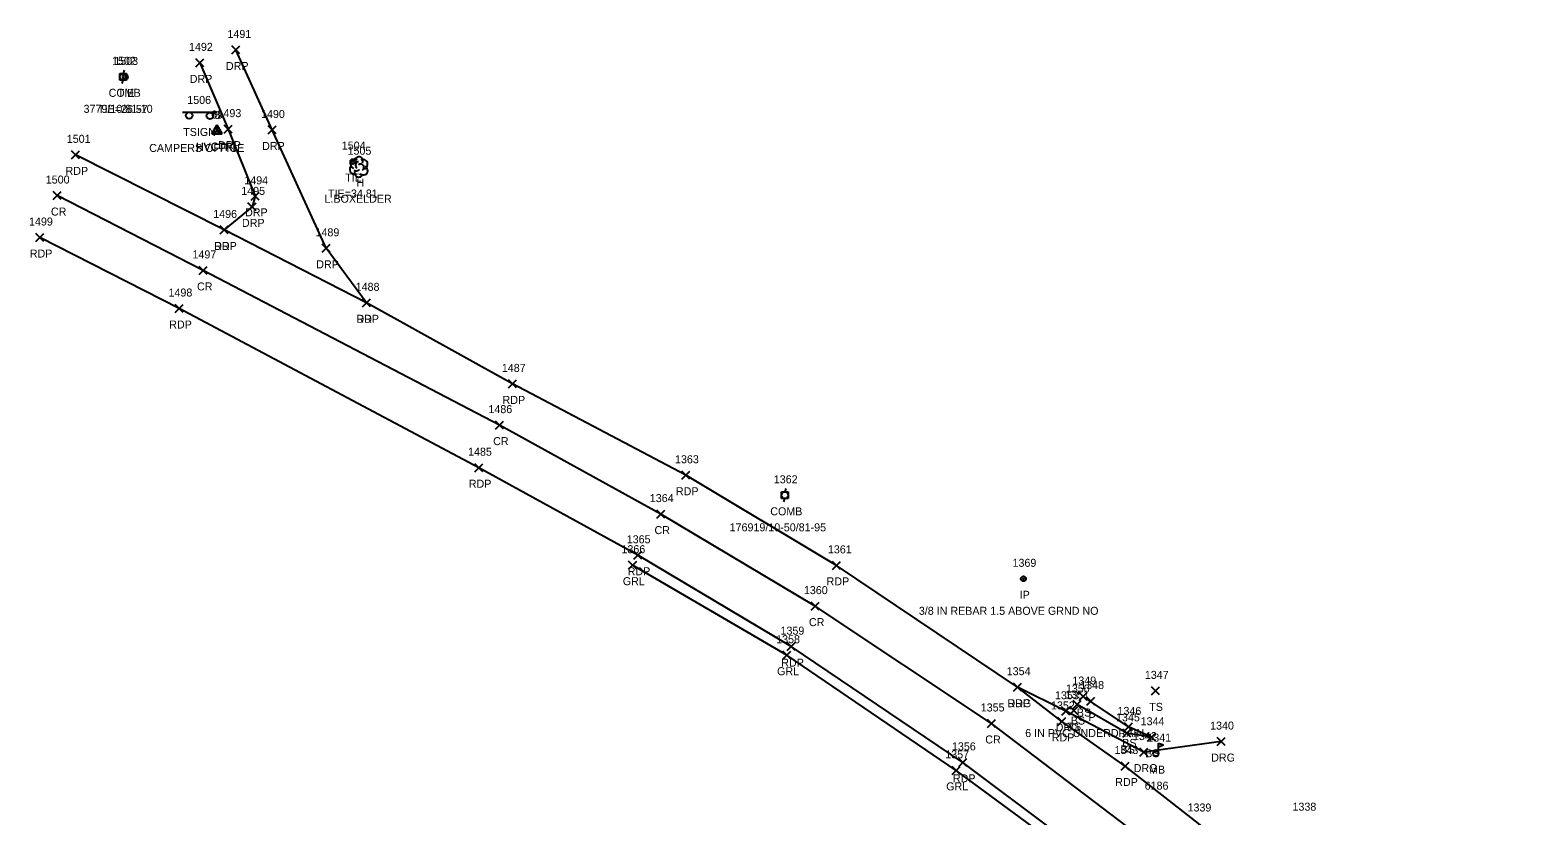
# Model space of a CAD drawing. Extents: x 1401404 to 1403982, y 557481 to 559873.
# Drawn here: x 1402764 to 1403136.9, y 558828.6 to 559024.9 of the extents above; entities that cross this region are included whole.
import ezdxf

# ---------------------------------------------------------------- set-up
doc = ezdxf.new("R2010")
doc.units = 0
for name, color, linetype in [('C_A', 7, 'Continuous'), ('C_C', 7, 'Continuous'), ('C_I', 7, 'Continuous'), ('CBP', 7, 'Continuous'), ('CPSM', 7, 'Continuous'), ('D_A', 7, 'Continuous'), ('D_C', 7, 'Continuous'), ('D_I', 7, 'Continuous'), ('D_TIC', 7, 'Continuous'), ('L_A', 7, 'Continuous'), ('L_C', 7, 'Continuous'), ('L_I', 7, 'Continuous'), ('L_TIC', 7, 'Continuous'), ('LELB', 7, 'Continuous'), ('LMB', 7, 'Continuous'), ('LTD', 7, 'Continuous'), ('M_A', 7, 'Continuous'), ('M_C', 7, 'Continuous'), ('M_I', 7, 'Continuous'), ('MPIR', 7, 'Continuous'), ('P_A', 7, 'Continuous'), ('P_I', 7, 'Continuous'), ('P_TIC', 7, 'Continuous'), ('PET', 7, 'Continuous'), ('PRC', 7, 'Continuous'), ('R_A', 7, 'Continuous'), ('R_I', 7, 'Continuous'), ('R_TIC', 7, 'Continuous'), ('RDG', 7, 'Continuous'), ('RDP', 7, 'Continuous'), ('RGR', 7, 'Continuous'), ('S_A', 7, 'Continuous'), ('S_C', 7, 'Continuous'), ('S_I', 7, 'Continuous'), ('SSGN', 7, 'Continuous'), ('U_A', 7, 'Continuous'), ('U_C', 7, 'Continuous'), ('U_I', 7, 'Continuous'), ('UP', 7, 'Continuous')]:
    doc.layers.add(name, color=color, linetype=linetype)

msp = doc.modelspace()

# ---------------------------------------------------------------- linework, layer by layer
at = {"layer": 'CBP'}
for centre, radius in [((1402787.85, 559013.09), 0.625), ((1402787.85, 559013.09), 0.0833), ((1402844.7, 558991.95), 0.625), ((1402844.7, 558991.95), 0.0833)]:
    msp.add_circle(centre, radius, dxfattribs=at)
at = {"layer": 'CPSM'}
for p, q in [((1402809.49, 558998.86), (1402810.74, 559001.02)), ((1402809.49, 558998.86), (1402810.74, 558999.58)), ((1402809.57, 558998.97), (1402810.82, 559001.13)), ((1402809.57, 558998.97), (1402810.82, 558999.69)), ((1402811.99, 558998.86), (1402810.74, 559001.02)), ((1402810.74, 558999.58), (1402810.74, 559001.02)), ((1402810.74, 558999.58), (1402810.74, 558999.58)), ((1402810.74, 558999.58), (1402811.99, 558998.86)), ((1402812.07, 558998.97), (1402810.82, 559001.13)), ((1402810.82, 558999.69), (1402810.82, 559001.13)), ((1402810.82, 558999.69), (1402810.82, 558999.69)), ((1402810.82, 558999.69), (1402812.07, 558998.97)), ((1402809.49, 558998.86), (1402811.99, 558998.86)), ((1402809.57, 558998.97), (1402812.07, 558998.97))]:
    msp.add_line(p, q, dxfattribs=at)
at = {"layer": 'D_TIC'}
for points in [[(1403028.12, 558856.1), (1403030.12, 558858.1)], [(1403030.12, 558856.1), (1403028.12, 558858.1)]]:
    msp.add_lwpolyline(points, dxfattribs=at)
at = {"layer": 'L_TIC'}
for points in [[(1403026.17, 558857.22), (1403028.17, 558859.22)], [(1403028.17, 558857.22), (1403026.17, 558859.22)], [(1403044.28, 558858.64), (1403046.28, 558860.64)], [(1403046.28, 558858.64), (1403044.28, 558860.64)], [(1403023.83, 558853.72), (1403025.83, 558855.72)], [(1403025.83, 558853.72), (1403023.83, 558855.72)], [(1403024.63, 558855.23), (1403026.63, 558857.23)], [(1403026.63, 558855.23), (1403024.63, 558857.23)], [(1403037.5, 558849.63), (1403039.5, 558851.63)], [(1403039.5, 558849.63), (1403037.5, 558851.63)], [(1403037.07, 558848.03), (1403039.07, 558850.03)], [(1403039.07, 558848.03), (1403037.07, 558850.03)], [(1403043.23, 558847.05), (1403045.23, 558849.05)], [(1403045.23, 558847.05), (1403043.23, 558849.05)], [(1403043.23, 558847.05), (1403045.23, 558849.05)], [(1403045.23, 558847.05), (1403043.23, 558849.05)]]:
    msp.add_lwpolyline(points, dxfattribs=at)
at = {"layer": 'LELB'}
for points in [[(1403044.23, 558848.05), (1403038.5, 558850.63), (1403027.17, 558858.22)], [(1403044.23, 558848.05), (1403038.07, 558849.03), (1403025.63, 558856.23)]]:
    msp.add_lwpolyline(points, dxfattribs=at)
at = {"layer": 'LMB'}
for p, q in [((1403045.33, 558843.95), (1403045.33, 558843.95)), ((1403045.98, 558846.55), (1403047.27, 558846.16)), ((1403045.98, 558843.95), (1403045.98, 558846.55)), ((1403045.98, 558845.65), (1403047.26, 558846.15))]:
    msp.add_line(p, q, dxfattribs=at)
msp.add_circle((1403045.33, 558843.95), 0.656, dxfattribs=at)
at = {"layer": 'LTD'}
msp.add_line((1402846.14, 558990.65), (1402846.14, 558990.65), dxfattribs=at)
msp.add_line((1402846.14, 558990.65), (1402846.14, 558990.65), dxfattribs=at)
msp.add_arc((1402846.19, 558992.09), 1.05, 335.5272, 180.9563, dxfattribs=at)
for centre, major_axis, ratio, start_param, end_param in [((1402845.35, 558991.32), (1.21, -0.51), 0.895232, 1.570796, 4.712389), ((1402847.18, 558991.24), (-1.14, -0.48), 0.949671, 1.570796, 4.712389), ((1402845.06, 558989.94), (0.58, -1.04), 0.959034, 3.141593, 6.283185), ((1402846.14, 558989.15), (0.26, 1.06), 0.942809, 1.570796, 4.712389), ((1402845.68, 558989.9), (-0.625, -0.083), 0.423636, 0, 3.141593), ((1402845.93, 558991.11), (-0.208, -0.792), 0.645439, 3.141593, 6.283185), ((1402846.64, 558990.48), (-0.5, 0.667), 0.989748, 3.141593, 6.283185), ((1402847.14, 558989.82), (-1.09, 0.79), 0.841452, 1.570796, 4.712389)]:
    msp.add_ellipse(centre, major_axis=major_axis, ratio=ratio, start_param=start_param, end_param=end_param, dxfattribs=at)
at = {"layer": 'MPIR'}
for radius in [0.625, 0.0833]:
    msp.add_circle((1403012.26, 558887.65), radius, dxfattribs=at)
at = {"layer": 'P_TIC'}
for points in [[(1402774.42, 558992.62), (1402776.42, 558994.62)], [(1402776.42, 558992.62), (1402774.42, 558994.62)], [(1402769.83, 558982.44), (1402771.83, 558984.44)], [(1402771.83, 558982.44), (1402769.83, 558984.44)], [(1402765.49, 558971.95), (1402767.49, 558973.95)], [(1402767.49, 558971.95), (1402765.49, 558973.95)], [(1402811.56, 558973.84), (1402813.56, 558975.84)], [(1402813.56, 558973.84), (1402811.56, 558975.84)], [(1402806.32, 558963.73), (1402808.32, 558965.73)], [(1402808.32, 558963.73), (1402806.32, 558965.73)], [(1402800.33, 558954.21), (1402802.33, 558956.21)], [(1402802.33, 558954.21), (1402800.33, 558956.21)], [(1402847.1, 558955.63), (1402849.1, 558957.63)], [(1402849.1, 558955.63), (1402847.1, 558957.63)], [(1402883.61, 558935.36), (1402885.61, 558937.36)], [(1402885.61, 558935.36), (1402883.61, 558937.36)], [(1402880.32, 558925.06), (1402882.32, 558927.06)], [(1402882.32, 558925.06), (1402880.32, 558927.06)], [(1402875.18, 558914.42), (1402877.18, 558916.42)], [(1402877.18, 558914.42), (1402875.18, 558916.42)], [(1402926.93, 558912.53), (1402928.93, 558914.53)], [(1402928.93, 558912.53), (1402926.93, 558914.53)], [(1402920.63, 558902.82), (1402922.63, 558904.82)], [(1402922.63, 558902.82), (1402920.63, 558904.82)], [(1402914.87, 558892.53), (1402916.87, 558894.53)], [(1402916.87, 558892.53), (1402914.87, 558894.53)], [(1402964.57, 558890.01), (1402966.57, 558892.01)], [(1402966.57, 558890.01), (1402964.57, 558892.01)], [(1402959.21, 558879.82), (1402961.21, 558881.82)], [(1402961.21, 558879.82), (1402959.21, 558881.82)], [(1402953.25, 558869.69), (1402955.25, 558871.69)], [(1402955.25, 558869.69), (1402953.25, 558871.69)], [(1403009.77, 558859.56), (1403011.77, 558861.56)], [(1403011.77, 558859.56), (1403009.77, 558861.56)], [(1403003.27, 558850.49), (1403005.27, 558852.49)], [(1403005.27, 558850.49), (1403003.27, 558852.49)], [(1403020.82, 558851), (1403022.82, 558853)], [(1403022.82, 558851), (1403020.82, 558853)], [(1402996.13, 558840.77), (1402998.13, 558842.77)], [(1402998.13, 558840.77), (1402996.13, 558842.77)], [(1403036.69, 558839.86), (1403038.69, 558841.86)], [(1403038.69, 558839.86), (1403036.69, 558841.86)]]:
    msp.add_lwpolyline(points, dxfattribs=at)
at = {"layer": 'PET'}
for points in [[(1403164.55, 558736.67), (1403129.25, 558765.78), (1403090.5, 558797.9), (1403080.9, 558805.87), (1403055.95, 558826.49), (1403037.69, 558840.86), (1403021.82, 558852), (1403010.77, 558860.56), (1402965.57, 558891.01), (1402927.93, 558913.53), (1402884.61, 558936.36), (1402848.1, 558956.63), (1402812.56, 558974.84), (1402775.42, 558993.62)], [(1403567.32, 558571.16), (1403521.05, 558571.89), (1403485.08, 558573.95), (1403437.34, 558577.29), (1403390.93, 558583.55), (1403361.61, 558591.03), (1403321.82, 558602.54), (1403283.74, 558620.33), (1403244.19, 558645.3), (1403219.22, 558663.61), (1403205.44, 558672.12), (1403186.06, 558688.41), (1403150.64, 558718.11), (1403114.18, 558748.06), (1403076.2, 558780.03), (1403043.94, 558806.7), (1402997.13, 558841.77), (1402954.25, 558870.69), (1402915.87, 558893.53), (1402876.18, 558915.42), (1402801.33, 558955.21), (1402766.49, 558972.95)]]:
    msp.add_lwpolyline(points, dxfattribs=at)
at = {"layer": 'PRC'}
msp.add_lwpolyline([(1403567.87, 558582.77), (1403521.72, 558584.55), (1403486.23, 558585.01), (1403438.97, 558588.43), (1403393.1, 558594.9), (1403360.83, 558602.71), (1403288.92, 558631.6), (1403250.3, 558655.21), (1403225.89, 558672.35), (1403193.37, 558698.04), (1403157.15, 558726.96), (1403121.95, 558757.26), (1403083.22, 558789.98), (1403051.1, 558815.94), (1403004.27, 558851.49), (1402960.21, 558880.82), (1402921.63, 558903.82), (1402881.32, 558926.06), (1402807.32, 558964.73), (1402770.83, 558983.44)], dxfattribs=at)
at = {"layer": 'R_TIC'}
for points in [[(1402814.49, 559018.83), (1402816.49, 559020.83)], [(1402816.49, 559018.83), (1402814.49, 559020.83)], [(1402805.45, 559015.61), (1402807.45, 559017.61)], [(1402807.45, 559015.61), (1402805.45, 559017.61)], [(1402812.57, 558999.04), (1402814.57, 559001.04)], [(1402814.57, 558999.04), (1402812.57, 559001.04)], [(1402823.54, 558998.83), (1402825.54, 559000.83)], [(1402825.54, 558998.83), (1402823.54, 559000.83)], [(1402818.5, 558979.61), (1402820.5, 558981.61)], [(1402820.5, 558979.61), (1402818.5, 558981.61)], [(1402819.27, 558982.25), (1402821.27, 558984.25)], [(1402821.27, 558982.25), (1402819.27, 558984.25)], [(1402811.56, 558973.84), (1402813.56, 558975.84)], [(1402813.56, 558973.84), (1402811.56, 558975.84)], [(1402837.07, 558969.26), (1402839.07, 558971.26)], [(1402839.07, 558969.26), (1402837.07, 558971.26)], [(1402847.1, 558955.63), (1402849.1, 558957.63)], [(1402849.1, 558955.63), (1402847.1, 558957.63)], [(1402913.61, 558890.05), (1402915.61, 558892.05)], [(1402915.61, 558890.05), (1402913.61, 558892.05)], [(1402952.15, 558867.55), (1402954.15, 558869.55)], [(1402954.15, 558867.55), (1402952.15, 558869.55)], [(1403009.77, 558859.56), (1403011.77, 558861.56)], [(1403011.77, 558859.56), (1403009.77, 558861.56)], [(1403021.81, 558853.54), (1403023.81, 558855.54)], [(1403023.81, 558853.54), (1403021.81, 558855.54)], [(1403060.67, 558845.97), (1403062.67, 558847.97)], [(1403062.67, 558845.97), (1403060.67, 558847.97)], [(1403041.3, 558843.34), (1403043.3, 558845.34)], [(1403043.3, 558843.34), (1403041.3, 558845.34)], [(1402994.41, 558838.77), (1402996.41, 558840.77)], [(1402996.41, 558838.77), (1402994.41, 558840.77)]]:
    msp.add_lwpolyline(points, dxfattribs=at)
at = {"layer": 'RDG'}
msp.add_lwpolyline([(1403061.67, 558846.97), (1403042.3, 558844.34), (1403022.81, 558854.54), (1403010.77, 558860.56)], dxfattribs=at)
at = {"layer": 'RDP'}
for points in [[(1402848.1, 558956.63), (1402838.07, 558970.26), (1402824.54, 558999.83), (1402815.49, 559019.83)], [(1402806.45, 559016.61), (1402813.57, 559000.04), (1402820.27, 558983.25), (1402819.5, 558980.61), (1402812.56, 558974.84)]]:
    msp.add_lwpolyline(points, dxfattribs=at)
at = {"layer": 'RGR'}
msp.add_lwpolyline([(1403051.95, 558793.15), (1403049.6, 558798.65), (1403044.94, 558803.35), (1402995.41, 558839.77), (1402953.15, 558868.55), (1402914.61, 558891.05)], dxfattribs=at)
at = {"layer": 'SSGN'}
for p, q in [((1402802.13, 559004.26), (1402810.72, 559004.26)), ((1402806.15, 559003.36), (1402806.15, 559003.36))]:
    msp.add_line(p, q, dxfattribs=at)
for centre in [(1402803.79, 559003.43), (1402809, 559003.36)]:
    msp.add_circle(centre, 0.833, dxfattribs=at)
at = {"layer": 'UP'}
for p, q in [((1402787.55, 559014.79), (1402787.3, 559013.95)), ((1402786.46, 559012.29), (1402786.46, 559013.95)), ((1402786.46, 559013.95), (1402788.13, 559013.95)), ((1402788.13, 559012.29), (1402786.46, 559012.29)), ((1402787.05, 559011.45), (1402787.3, 559012.29)), ((1402787.3, 559013.12), (1402787.3, 559013.12)), ((1402788.13, 559013.95), (1402788.13, 559012.29)), ((1402952.86, 558910.19), (1402952.61, 558909.36)), ((1402951.77, 558907.69), (1402951.77, 558909.36)), ((1402951.77, 558909.36), (1402953.44, 558909.36)), ((1402953.44, 558907.69), (1402951.77, 558907.69)), ((1402952.36, 558906.86), (1402952.61, 558907.69)), ((1402952.61, 558908.52), (1402952.61, 558908.52)), ((1402953.44, 558909.36), (1402953.44, 558907.69))]:
    msp.add_line(p, q, dxfattribs=at)
for centre in [(1402787.3, 559013.12), (1402952.61, 558908.52)]:
    msp.add_circle(centre, 0.833, dxfattribs=at)

# ---------------------------------------------------------------- texts
at = {"layer": 'C_A'}
for s, p in [('TIE', (1402785.93, 559008.09)), ('HVCTRL', (1402805.43, 558994.58)), ('HVCTRL', (1402805.51, 558994.69)), ('TIE', (1402842.78, 558986.95))]:
    msp.add_text(s, height=2, dxfattribs=at).set_placement(p)
at = {"layer": 'C_C'}
for s, p in [('TIE=26.57', (1402781.03, 559004.09)), ('TIE=34.81', (1402838.5, 558982.95))]:
    msp.add_text(s, height=2, dxfattribs=at).set_placement(p)
at = {"layer": 'C_I'}
for s, p in [('1503', (1402785.08, 559016.09)), ('69', (1402809.3, 559002.69)), ('8', (1402810.17, 559002.58)), ('1504', (1402841.93, 558994.95))]:
    msp.add_text(s, height=2, dxfattribs=at).set_placement(p)
at = {"layer": 'D_A'}
msp.add_text('P', height=2, dxfattribs=at).set_placement((1403028.5, 558852.1))
at = {"layer": 'D_C'}
msp.add_text('6 IN PVC UNDERDRAIN', height=2, dxfattribs=at).set_placement((1403012.69, 558848.1))
at = {"layer": 'D_I'}
msp.add_text('1348', height=2, dxfattribs=at).set_placement((1403026.43, 558860.1))
at = {"layer": 'L_A'}
for s, p in [('H', (1402845.57, 558985.65)), ('BS', (1403025.61, 558853.22)), ('TS', (1403043.68, 558854.64)), ('TS', (1403023.24, 558849.72)), ('BS', (1403024.07, 558851.23)), ('BS', (1403036.94, 558845.63)), ('BS', (1403036.51, 558844.03)), ('BS', (1403042.67, 558843.05)), ('BS', (1403042.67, 558843.05)), ('MB', (1403043.63, 558838.95))]:
    msp.add_text(s, height=2, dxfattribs=at).set_placement(p)
at = {"layer": 'L_C'}
for s, p in [('L.BOXELDER', (1402837.61, 558981.65)), ('6186', (1403042.53, 558834.95))]:
    msp.add_text(s, height=2, dxfattribs=at).set_placement(p)
at = {"layer": 'L_I'}
for s, p in [('1505', (1402843.37, 558993.65)), ('1349', (1403024.47, 558861.22)), ('1347', (1403042.58, 558862.64)), ('1351', (1403022.71, 558857.72)), ('1350', (1403022.85, 558859.23)), ('1346', (1403035.75, 558853.63)), ('1345', (1403035.38, 558852.03)), ('1344', (1403041.53, 558851.05)), ('1344', (1403041.53, 558851.05)), ('1341', (1403043.2, 558846.95)), ('1338', (1403079.47, 558829.69)), ('1338', (1403079.47, 558829.69))]:
    msp.add_text(s, height=2, dxfattribs=at).set_placement(p)
at = {"layer": 'M_A'}
msp.add_text('IP', height=2, dxfattribs=at).set_placement((1403011.31, 558882.65))
at = {"layer": 'M_C'}
msp.add_text('3/8 IN REBAR 1.5 ABOVE GRND NO', height=2, dxfattribs=at).set_placement((1402986.11, 558878.65))
at = {"layer": 'M_I'}
msp.add_text('1369', height=2, dxfattribs=at).set_placement((1403009.52, 558890.65))
at = {"layer": 'P_A'}
for s, p in [('RDP', (1402772.91, 558988.62)), ('CR', (1402769.26, 558978.44)), ('RDP', (1402763.98, 558967.95)), ('RDP', (1402810.05, 558969.84)), ('CR', (1402805.76, 558959.73)), ('RDP', (1402798.82, 558950.21)), ('RDP', (1402845.59, 558951.63)), ('RDP', (1402882.1, 558931.36)), ('CR', (1402879.75, 558921.06)), ('RDP', (1402873.67, 558910.42)), ('RDP', (1402925.42, 558908.53)), ('CR', (1402920.07, 558898.82)), ('RDP', (1402913.36, 558888.53)), ('RDP', (1402963.06, 558886.01)), ('CR', (1402958.65, 558875.82)), ('RDP', (1402951.73, 558865.69)), ('RDP', (1403008.25, 558855.56)), ('CR', (1403002.71, 558846.49)), ('RDP', (1403019.31, 558847)), ('RDP', (1402994.62, 558836.77)), ('RDP', (1403035.18, 558835.86))]:
    msp.add_text(s, height=2, dxfattribs=at).set_placement(p)
at = {"layer": 'P_I'}
for s, p in [('1501', (1402773.22, 558996.62)), ('1500', (1402767.97, 558986.44)), ('1499', (1402763.79, 558975.95)), ('1496', (1402809.81, 558977.84)), ('1497', (1402804.63, 558967.73)), ('1498', (1402798.64, 558958.21)), ('1488', (1402845.4, 558959.63)), ('1487', (1402881.92, 558939.36)), ('1486', (1402878.57, 558929.06)), ('1485', (1402873.49, 558918.42)), ('1363', (1402925.19, 558916.53)), ('1364', (1402918.89, 558906.82)), ('1365', (1402913.13, 558896.53)), ('1361', (1402963.39, 558894.01)), ('1360', (1402957.39, 558883.82)), ('1359', (1402951.55, 558873.69)), ('1354', (1403008.07, 558863.56)), ('1355', (1403001.58, 558854.49)), ('1352', (1403019.13, 558855)), ('1356', (1402994.38, 558844.77)), ('1343', (1403035, 558843.86)), ('1339', (1403053.25, 558829.49))]:
    msp.add_text(s, height=2, dxfattribs=at).set_placement(p)
at = {"layer": 'R_A'}
for s, p in [('DRP', (1402812.98, 559014.83)), ('DRP', (1402803.94, 559011.61)), ('DRP', (1402811.06, 558995.04)), ('DRP', (1402822.03, 558994.83)), ('DRP', (1402816.99, 558975.61)), ('DRP', (1402817.76, 558978.25)), ('DRP', (1402810.05, 558969.84)), ('DRP', (1402835.56, 558965.26)), ('DRP', (1402845.59, 558951.63)), ('GRL', (1402912.15, 558886.05)), ('GRL', (1402950.69, 558863.55)), ('DRG', (1403008.25, 558855.56)), ('DRG', (1403020.3, 558849.54)), ('DRG', (1403059.15, 558841.97)), ('DRG', (1403039.79, 558839.34)), ('GRL', (1402992.95, 558834.77))]:
    msp.add_text(s, height=2, dxfattribs=at).set_placement(p)
at = {"layer": 'R_I'}
for s, p in [('1491', (1402813.37, 559022.83)), ('1492', (1402803.76, 559019.61)), ('1493', (1402810.88, 559003.04)), ('1490', (1402821.76, 559002.83)), ('1495', (1402816.81, 558983.61)), ('1494', (1402817.58, 558986.25)), ('1496', (1402809.81, 558977.84)), ('1489', (1402835.37, 558973.26)), ('1488', (1402845.4, 558959.63)), ('1366', (1402911.81, 558894.05)), ('1358', (1402950.46, 558871.55)), ('1354', (1403008.07, 558863.56)), ('1353', (1403020.12, 558857.54)), ('1340', (1403058.89, 558849.97)), ('1342', (1403039.6, 558847.34)), ('1357', (1402992.71, 558842.77)), ('1338', (1403079.47, 558829.69))]:
    msp.add_text(s, height=2, dxfattribs=at).set_placement(p)
at = {"layer": 'S_A'}
msp.add_text('TSIGN', height=2, dxfattribs=at).set_placement((1402802.32, 558998.34))
at = {"layer": 'S_C'}
msp.add_text('CAMPERS OFFICE', height=2, dxfattribs=at).set_placement((1402793.81, 558994.34))
at = {"layer": 'S_I'}
msp.add_text('1506', height=2, dxfattribs=at).set_placement((1402803.32, 559006.34))
at = {"layer": 'U_A'}
for p in [(1402783.68, 559008.12), (1402948.99, 558903.52)]:
    msp.add_text('COMB', height=2, dxfattribs=at).set_placement(p)
at = {"layer": 'U_C'}
for s, p in [('3779/10/81-10', (1402777.42, 559004.12)), ('176919/10-50/81-95', (1402938.84, 558899.52))]:
    msp.add_text(s, height=2, dxfattribs=at).set_placement(p)
at = {"layer": 'U_I'}
for s, p in [('1502', (1402784.53, 559016.12)), ('1362', (1402949.87, 558911.52))]:
    msp.add_text(s, height=2, dxfattribs=at).set_placement(p)

doc.saveas('drawing.dxf')
